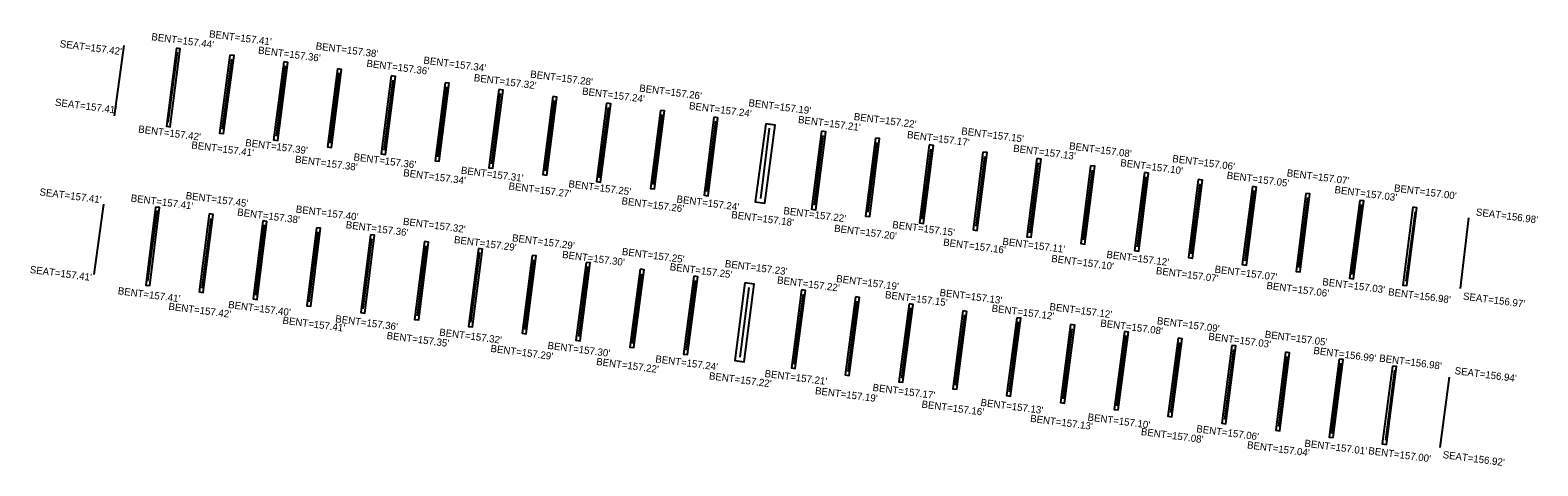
# Model space of a CAD drawing. Extents: x 2107167 to 2121551, y 865392 to 868477.
# Drawn here: x 2118336 to 2119170, y 867915 to 868156 of the extents above; entities that cross this region are included whole.
import ezdxf

# ---------------------------------------------------------------- set-up
doc = ezdxf.new("R2010")
doc.units = 0
for name, color, linetype in [('RD_EX_Bridge', 7, 'Continuous'), ('RD_EX_Bridge_txCode', 7, 'Continuous'), ('RD_EX_Conc', 7, 'Continuous')]:
    doc.layers.add(name, color=color, linetype=linetype)

msp = doc.modelspace()

# ---------------------------------------------------------------- linework, layer by layer
at = {"layer": 'RD_EX_Bridge'}
for p, q in [((2118382.41, 868108.64), (2118387.71, 868147.56)), ((2118412.15, 868104.87), (2118417.34, 868143.75)), ((2118447.16, 868139.87), (2118441.96, 868101.25)), ((2118476.84, 868136.2), (2118471.81, 868097.35)), ((2118506.56, 868132.3), (2118501.64, 868093.49)), ((2118536.34, 868128.37), (2118531.37, 868089.7)), ((2118566.16, 868124.7), (2118561.19, 868085.89)), ((2118595.88, 868120.87), (2118590.94, 868082.01)), ((2118625.7, 868117.11), (2118620.65, 868078.24)), ((2118655.48, 868113.28), (2118650.44, 868074.44)), ((2118685.27, 868109.42), (2118680.27, 868070.66)), ((2118714.91, 868105.74), (2118709.95, 868066.73)), ((2118744.64, 868101.83), (2118739.81, 868062.91)), ((2118774.31, 868097.83), (2118769.53, 868059.18)), ((2118804.14, 868093.87), (2118799.29, 868055.33)), ((2118833.98, 868090.25), (2118829.1, 868051.42)), ((2118863.69, 868086.22), (2118858.87, 868047.63)), ((2118893.48, 868082.57), (2118888.61, 868043.89)), ((2118923.27, 868078.6), (2118918.29, 868040.02)), ((2118953.02, 868074.89), (2118948.17, 868036.18)), ((2118982.81, 868071.03), (2118977.92, 868032.4)), ((2119012.75, 868067.38), (2119007.74, 868028.5)), ((2118371.14, 868020.89), (2118376.51, 868059.72)), ((2119042.4, 868063.46), (2119037.52, 868024.78)), ((2119072.17, 868059.59), (2119067.04, 868020.87)), ((2118405.91, 868056.27), (2118400.79, 868017.15)), ((2118435.65, 868051.88), (2118430.67, 868013.33)), ((2118465.32, 868048.29), (2118460.47, 868009.57)), ((2119101.91, 868055.69), (2119096.8, 868017.22)), ((2119131.53, 868052.15), (2119126.81, 868013.11)), ((2118490.17, 868005.77), (2118495.08, 868044.5)), ((2118519.98, 868002.03), (2118524.83, 868040.69)), ((2118554.62, 868036.75), (2118549.8, 867998.13)), ((2118579.53, 867994.38), (2118584.63, 868033)), ((2118614.33, 868029.01), (2118609.32, 867990.49)), ((2118644.19, 868025.27), (2118639.08, 867986.73)), ((2118673.95, 868021.34), (2118668.86, 867982.85)), ((2118703.7, 868017.66), (2118698.65, 867979.03)), ((2118733.46, 868013.71), (2118728.36, 867975.24)), ((2118763.35, 868010.08), (2118758.27, 867971.39)), ((2118793.09, 868006.2), (2118788.06, 867967.39)), ((2118822.86, 868002.47), (2118817.76, 867963.67)), ((2118852.62, 867998.56), (2118847.54, 867959.81)), ((2118882.43, 867994.78), (2118877.34, 867956.03)), ((2118912.15, 867990.87), (2118907.09, 867952.2)), ((2118941.91, 867987.12), (2118936.82, 867948.42)), ((2118971.67, 867983.28), (2118966.61, 867944.6)), ((2119001.47, 867979.48), (2118996.51, 867940.75)), ((2119031.08, 867975.6), (2119026.41, 867936.84)), ((2119060.78, 867971.91), (2119055.77, 867933.11)), ((2119090.53, 867967.99), (2119085.57, 867929.44)), ((2119120.73, 867964.2), (2119115.65, 867925.27))]:
    msp.add_line(p, q, dxfattribs=at)
at = {"layer": 'RD_EX_Conc'}
for points in [[(2118416.74, 868146), (2118411.24, 868102.84), (2118413.28, 868102.58), (2118418.78, 868145.74)], [(2118446.32, 868142.2), (2118440.53, 868099.11), (2118442.82, 868098.8), (2118448.61, 868141.89)], [(2118476.07, 868138.43), (2118470.48, 868095.29), (2118472.74, 868095), (2118478.33, 868138.13)], [(2118505.88, 868134.51), (2118500.32, 868091.41), (2118502.56, 868091.13), (2118508.11, 868134.22)], [(2118535.57, 868130.73), (2118530.04, 868087.6), (2118532.29, 868087.31), (2118537.82, 868130.44)], [(2118565.3, 868126.93), (2118559.79, 868083.81), (2118562.02, 868083.52), (2118567.54, 868126.65)], [(2118595.1, 868123.19), (2118589.51, 868079.96), (2118591.82, 868079.66), (2118597.41, 868122.89)], [(2118624.93, 868119.3), (2118619.32, 868076.14), (2118621.56, 868075.85), (2118627.16, 868119.01)], [(2118654.69, 868115.55), (2118649.12, 868072.31), (2118651.38, 868072.02), (2118656.94, 868115.26)], [(2118684.53, 868111.62), (2118678.91, 868068.5), (2118681.14, 868068.21), (2118686.76, 868111.33)], [(2118714.03, 868107.86), (2118708.63, 868064.71), (2118710.86, 868064.43), (2118716.26, 868107.58)], [(2118742.74, 868104.24), (2118736.88, 868061.07), (2118742.15, 868060.36), (2118748.01, 868103.53)], [(2118773.65, 868100.1), (2118768.13, 868057.02), (2118770.42, 868056.73), (2118775.93, 868099.81)], [(2118803.42, 868096.31), (2118797.91, 868053.23), (2118800.23, 868052.93), (2118805.74, 868096.02)], [(2118833.18, 868092.5), (2118827.72, 868049.39), (2118830.04, 868049.09), (2118835.5, 868092.2)], [(2118862.88, 868088.58), (2118857.48, 868045.59), (2118859.75, 868045.31), (2118865.16, 868088.29)], [(2118892.72, 868084.97), (2118887.22, 868041.83), (2118889.55, 868041.54), (2118895.05, 868084.67)], [(2118922.45, 868081.06), (2118916.98, 868038.02), (2118919.27, 868037.73), (2118924.73, 868080.77)], [(2118952.25, 868077.22), (2118946.78, 868034.1), (2118949.05, 868033.82), (2118954.52, 868076.93)], [(2118982.02, 868073.41), (2118976.57, 868030.26), (2118978.85, 868029.97), (2118984.29, 868073.12)], [(2119011.92, 868069.51), (2119006.37, 868026.44), (2119008.64, 868026.15), (2119014.19, 868069.22)], [(2119041.49, 868065.7), (2119036.15, 868022.67), (2119038.44, 868022.39), (2119043.77, 868065.42)], [(2118405.15, 868058.15), (2118399.69, 868015.09), (2118401.94, 868014.81), (2118407.39, 868057.87)], [(2119071.37, 868061.87), (2119065.66, 868018.91), (2119067.97, 868018.6), (2119073.68, 868061.56)], [(2119100.74, 868058.08), (2119095.19, 868015.07), (2119097.45, 868014.78), (2119103, 868057.78)], [(2118434.89, 868054.37), (2118429.31, 868011.32), (2118431.55, 868011.03), (2118437.12, 868054.08)], [(2118464.51, 868050.56), (2118459.12, 868007.47), (2118461.34, 868007.19), (2118466.73, 868050.28)], [(2118494.23, 868046.8), (2118488.91, 868003.67), (2118491.11, 868003.4), (2118496.44, 868046.53)], [(2118524.04, 868042.92), (2118518.72, 867999.86), (2118520.91, 867999.58), (2118526.23, 868042.65)], [(2118553.86, 868039.11), (2118548.5, 867996.06), (2118550.72, 867995.78), (2118556.08, 868038.84)], [(2118583.81, 868035.24), (2118578.21, 867992.27), (2118580.43, 867991.98), (2118586.03, 868034.95)], [(2118613.55, 868031.49), (2118608.05, 867988.45), (2118610.15, 867988.18), (2118615.65, 868031.22)], [(2118643.37, 868027.58), (2118637.74, 867984.61), (2118639.99, 867984.32), (2118645.61, 868027.29)], [(2118673.19, 868023.78), (2118667.48, 867980.81), (2118669.75, 867980.51), (2118675.46, 868023.48)], [(2118702.88, 868020), (2118697.3, 867976.96), (2118699.49, 867976.68), (2118705.07, 868019.71)], [(2118731.22, 868016.25), (2118725.69, 867973.34), (2118730.81, 867972.68), (2118736.34, 868015.59)], [(2118762.55, 868012.39), (2118756.89, 867969.32), (2118759.08, 867969.03), (2118764.75, 868012.1)], [(2118792.31, 868008.54), (2118786.73, 867965.47), (2118788.94, 867965.18), (2118794.52, 868008.25)], [(2118822.07, 868004.67), (2118816.41, 867961.62), (2118818.63, 867961.33), (2118824.29, 868004.37)], [(2118851.82, 868000.81), (2118846.2, 867957.74), (2118848.41, 867957.46), (2118854.02, 868000.53)], [(2118881.56, 867997.05), (2118875.96, 867953.99), (2118878.17, 867953.7), (2118883.77, 867996.76)], [(2118911.38, 867993.26), (2118905.71, 867950.16), (2118908.02, 867949.85), (2118913.69, 867992.95)], [(2118941.13, 867989.38), (2118935.42, 867946.35), (2118937.71, 867946.05), (2118943.43, 867989.07)], [(2118970.87, 867985.7), (2118965.23, 867942.58), (2118967.43, 867942.29), (2118973.07, 867985.41)], [(2119000.65, 867981.74), (2118995.07, 867938.72), (2118997.28, 867938.44), (2119002.85, 867981.46)], [(2119030.2, 867977.94), (2119024.98, 867934.83), (2119027.19, 867934.57), (2119032.41, 867977.67)], [(2119059.89, 867974.18), (2119054.39, 867931.06), (2119056.68, 867930.77), (2119062.18, 867973.89)], [(2119089.44, 867970.33), (2119083.79, 867927.28), (2119086.07, 867926.99), (2119091.71, 867970.03)]]:
    msp.add_lwpolyline(points, close=True, dxfattribs=at)

# ---------------------------------------------------------------- texts
at = {"layer": 'RD_EX_Bridge_txCode'}
for s, p in [("SEAT=157.42'", (2118352.01, 868146.61)), ("BENT=157.44'", (2118402.66, 868150.47)), ("BENT=157.41'", (2118434.6, 868152.05)), ("BENT=157.38'", (2118493.57, 868145.35)), ("BENT=157.36'", (2118461.69, 868143.03)), ("BENT=157.34'", (2118553.2, 868137.51)), ("BENT=157.36'", (2118521.69, 868135.77)), ("BENT=157.32'", (2118581.06, 868127.84)), ("BENT=157.28'", (2118612.26, 868129.81)), ("BENT=157.24'", (2118640.96, 868120.41)), ("BENT=157.26'", (2118672.58, 868122.08)), ("SEAT=157.41'", (2118349.36, 868114.27)), ("BENT=157.24'", (2118700.12, 868112.33)), ("BENT=157.19'", (2118733, 868113.96)), ("BENT=157.21'", (2118760.42, 868104.71)), ("BENT=157.22'", (2118791.27, 868106.36)), ("BENT=157.42'", (2118395.4, 868099.42)), ("BENT=157.17'", (2118820.7, 868096.36)), ("BENT=157.15'", (2118850.72, 868098.37)), ("BENT=157.41'", (2118424.77, 868090.64)), ("BENT=157.39'", (2118454.59, 868091.93)), ("BENT=157.13'", (2118879.43, 868088.83)), ("BENT=157.08'", (2118910.37, 868090.12)), ("BENT=157.38'", (2118482.15, 868082.75)), ("BENT=157.36'", (2118514.52, 868084.03)), ("BENT=157.10'", (2118938.7, 868080.8)), ("BENT=157.06'", (2118967.48, 868083.09)), ("BENT=157.34'", (2118542, 868075.28)), ("BENT=157.31'", (2118573.9, 868076.66)), ("BENT=157.05'", (2118997.55, 868073.87)), ("BENT=157.07'", (2119030.77, 868075.21)), ("SEAT=157.41'", (2118340.78, 868064.72)), ("BENT=157.41'", (2118391.24, 868061.32)), ("BENT=157.45'", (2118421.66, 868062.66)), ("BENT=157.27'", (2118600.27, 868067.97)), ("BENT=157.25'", (2118633.41, 868069.17)), ("BENT=157.03'", (2119057.2, 868065.97)), ("BENT=157.00'", (2119090.11, 868066.86)), ("BENT=157.38'", (2118450.16, 868053.56)), ("BENT=157.40'", (2118482.57, 868055.21)), ("BENT=157.26'", (2118662.77, 868059.74)), ("BENT=157.24'", (2118693.2, 868060.75)), ("BENT=157.22'", (2118752.34, 868054.31)), ("SEAT=156.98'", (2119135.43, 868053.59)), ("BENT=157.36'", (2118510.22, 868046.56)), ("BENT=157.32'", (2118541.86, 868048.41)), ("BENT=157.18'", (2118723.48, 868052.12)), ("BENT=157.20'", (2118780.39, 868044.62)), ("BENT=157.15'", (2118812.55, 868046.59)), ("BENT=157.29'", (2118570.08, 868038.33)), ("BENT=157.29'", (2118602.22, 868039.31)), ("BENT=157.16'", (2118840.72, 868036.92)), ("BENT=157.11'", (2118873.51, 868037.37)), ("BENT=157.30'", (2118629.91, 868030.12)), ("BENT=157.25'", (2118662.97, 868031.76)), ("BENT=157.10'", (2118900.5, 868027.91)), ("BENT=157.12'", (2118931.05, 868030.15)), ("SEAT=157.41'", (2118335.42, 868021.8)), ("BENT=157.25'", (2118689.46, 868023.34)), ("BENT=157.23'", (2118719.93, 868025.06)), ("BENT=157.07'", (2118958.4, 868021.18)), ("BENT=157.07'", (2118990.87, 868021.98)), ("BENT=157.22'", (2118748.83, 868015.99)), ("BENT=157.19'", (2118781.54, 868016.78)), ("BENT=157.06'", (2119019.57, 868012.98)), ("BENT=157.03'", (2119050.48, 868015.03)), ("BENT=157.41'", (2118384.1, 868010.04)), ("BENT=157.15'", (2118808.54, 868007.88)), ("BENT=157.13'", (2118838.74, 868009.12)), ("BENT=156.98'", (2119086.87, 868009.47)), ("SEAT=156.97'", (2119128.31, 868007.08)), ("BENT=157.42'", (2118412.13, 868001.46)), ("BENT=157.40'", (2118445.15, 868002.45)), ("BENT=157.36'", (2118504.42, 867994.56)), ("BENT=157.12'", (2118867.52, 868000.4)), ("BENT=157.12'", (2118899.52, 868001.28)), ("BENT=157.41'", (2118475.24, 867993.76)), ("BENT=157.32'", (2118561.93, 867987.17)), ("BENT=157.08'", (2118927.63, 867992.19)), ("BENT=157.09'", (2118958.97, 867993.49)), ("BENT=157.05'", (2119018.62, 867986)), ("BENT=157.35'", (2118532.81, 867985.33)), ("BENT=157.29'", (2118590.29, 867978.2)), ("BENT=157.30'", (2118621.85, 867979.85)), ("BENT=157.03'", (2118987.42, 867984.85)), ("BENT=157.22'", (2118648.76, 867970.97)), ("BENT=157.24'", (2118681.47, 867972.37)), ("BENT=156.99'", (2119045.55, 867977.07)), ("BENT=156.98'", (2119081.93, 867972.86)), ("BENT=157.22'", (2118711.14, 867963.04)), ("BENT=157.21'", (2118741.92, 867964.33)), ("SEAT=156.94'", (2119123.65, 867965.91)), ("BENT=157.19'", (2118769.82, 867954.86)), ("BENT=157.17'", (2118801.67, 867956.62)), ("BENT=157.16'", (2118828.73, 867947.39)), ("BENT=157.13'", (2118861.41, 867948.35)), ("BENT=157.13'", (2118888.83, 867939.53)), ("BENT=157.10'", (2118920.61, 867940.26)), ("BENT=157.08'", (2118950.08, 867932.23)), ("BENT=157.06'", (2118980.76, 867933.78)), ("BENT=157.04'", (2119008.82, 867924.86)), ("BENT=157.01'", (2119040.58, 867925.79)), ("BENT=157.00'", (2119075.92, 867921.64)), ("SEAT=156.92'", (2119117.02, 867919.47))]:
    msp.add_text(s, height=4, rotation=352.57469, dxfattribs=at).set_placement(p)

doc.saveas('drawing.dxf')
